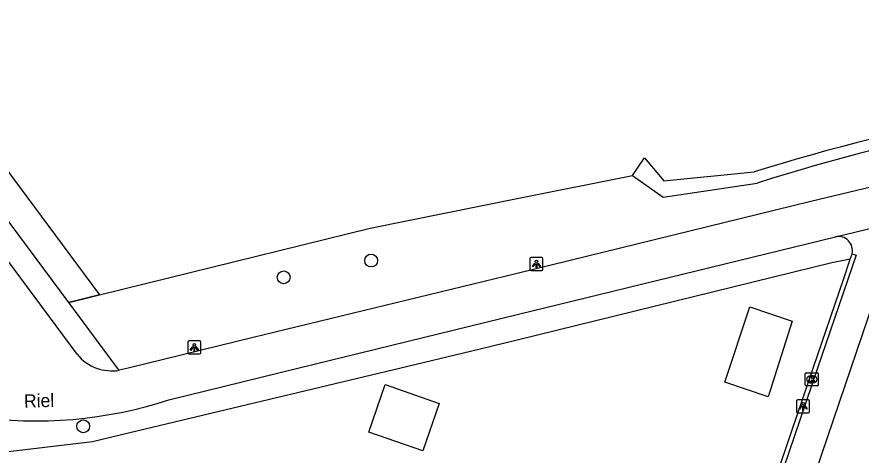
# Model space of a CAD drawing. Extents: x 163427 to 164190, y 380331 to 381641.
# Drawn here: x 163961.9 to 164026.2, y 380993.4 to 381026.8 of the extents above; entities that cross this region are included whole.
import ezdxf

# ---------------------------------------------------------------- set-up
doc = ezdxf.new("R2010")
doc.units = 0
for name, color, linetype in [('IMGEO_Boom', 7, 'Continuous'), ('IMGEO_Fietspad_open', 7, 'Continuous'), ('IMGEO_Groenvoorziening', 7, 'Continuous'), ('IMGEO_Hek', 7, 'Continuous'), ('IMGEO_Kolk', 7, 'Continuous'), ('IMGEO_Lichtpunt', 7, 'Continuous'), ('IMGEO_Openbare_ruimte_label', 7, 'Continuous'), ('IMGEO_Pand', 7, 'Continuous'), ('IMGEO_Rijbaan_lokaal_open', 7, 'Continuous'), ('IMGEO_Voetpad_open', 7, 'Continuous'), ('IMGEO_Waterloop', 7, 'Continuous')]:
    doc.layers.add(name, color=color, linetype=linetype)

msp = doc.modelspace()

# ---------------------------------------------------------------- linework, layer by layer
at = {"layer": 'IMGEO_Boom'}
for centre in [(163988.865, 381008.202), (163982.196, 381006.926), (163966.911, 380995.571)]:
    msp.add_circle(centre, 0.489, dxfattribs=at)
at = {"layer": 'IMGEO_Fietspad_open'}
for points in [[(163966.446, 381001.057), (163930.523, 381049.491), (163926.717, 381054.622), (163925.556, 381056.187)], [(164038.024, 381016.446), (164022.398, 381012.694), (164000, 381007.225), (163979.878, 381002.33), (163970.33, 381000), (163969.654, 380999.835)], [(164024.271, 381010.02), (164029.636, 381011.297)], [(163973.446, 380997.596), (163983.281, 381000), (164000, 381004.087), (164024.271, 381010.02)]]:
    msp.add_lwpolyline(points, dxfattribs=at)
for centre, radius, start, end in [((163969.159, 381003.295), 3.517, 219.52759, 249.55059), ((163969.115, 381003.289), 3.495, 250.18958, 278.87643), ((163963.36, 381028.213), 32.235, 261.55505, 288.23327)]:
    msp.add_arc(centre, radius, start, end, dxfattribs=at)
at = {"layer": 'IMGEO_Groenvoorziening'}
for points in [[(163936.474, 381048.305), (163965.302, 381009.415), (163968.142, 381005.578)], [(163968.142, 381005.578), (163988.801, 381010.675), (164000, 381012.925), (164008.796, 381014.693)], [(164025.394, 381008.299), (164023.996, 381008.024), (164000, 381002.141), (163996.432, 381001.266), (163991.135, 381000), (163970.466, 380995.06), (163967.625, 380994.381), (163961.405, 380993.65), (163960.215, 380993.613), (163954.592, 380993.795), (163949.019, 380994.564), (163937.098, 380997.759), (163924.687, 381000), (163899.949, 381004.467), (163899.243, 381001.078)], [(163968.142, 381005.578), (163965.814, 381005.004)]]:
    msp.add_lwpolyline(points, dxfattribs=at)
at = {"layer": 'IMGEO_Hek'}
msp.add_lwpolyline([(163965.814, 381005.004), (163968.142, 381005.578)], dxfattribs=at)
at = {"layer": 'IMGEO_Kolk'}
for p, q in [((164021.963, 380998.727), (164021.963, 380999.579)), ((164022.038, 380999.653), (164022.89, 380999.653)), ((164022.964, 380999.579), (164022.964, 380998.727)), ((164022.451, 380999.433), (164022.476, 380999.433)), ((164022.89, 380998.653), (164022.038, 380998.653)), ((164022.474, 380998.873), (164022.449, 380998.873))]:
    msp.add_line(p, q, dxfattribs=at)
for points in [[(164021.963, 380998.727), (164021.963, 380999.579)], [(164022.038, 380999.653), (164022.89, 380999.653)], [(164022.964, 380999.579), (164022.964, 380998.727)], [(164022.284, 380999.353), (164022.407, 380999.353), (164022.407, 380999.202), (164022.537, 380999.353), (164022.701, 380999.353), (164022.555, 380999.202), (164022.708, 380998.953), (164022.556, 380998.953), (164022.471, 380999.117), (164022.407, 380999.05), (164022.407, 380998.953), (164022.284, 380998.953), (164022.284, 380999.353)], [(164022.89, 380998.653), (164022.038, 380998.653)]]:
    msp.add_lwpolyline(points, dxfattribs=at)
for centre, start, end in [((164022.04, 380999.577), 91.55205, 178.44795), ((164022.04, 380999.577), 91.55205, 178.44795), ((164022.888, 380999.577), 1.55205, 88.44795), ((164022.888, 380999.577), 1.55205, 88.44795), ((164022.04, 380998.729), 181.55205, 268.44795), ((164022.04, 380998.729), 181.55205, 268.44795), ((164022.888, 380998.729), 271.55205, 358.44795), ((164022.888, 380998.729), 271.55205, 358.44795)]:
    msp.add_arc(centre, 0.0765, start, end, dxfattribs=at)
for centre, major_axis, ratio, start_param, end_param in [((164022.45, 380999.153), (-0.387, 0.002), 0.722429, 4.712389, 7.853982), ((164022.475, 380999.153), (-0.39, 0.002), 0.717154, 1.570796, 4.712389)]:
    msp.add_ellipse(centre, major_axis=major_axis, ratio=ratio, start_param=start_param, end_param=end_param, dxfattribs=at)
at = {"layer": 'IMGEO_Lichtpunt'}
for p, q in [((164000.97, 381008.347), (164000.97, 381007.54)), ((164000.97, 381008.347), (164000.97, 381007.54)), ((164001.872, 381008.442), (164001.064, 381008.442)), ((164001.872, 381008.442), (164001.064, 381008.442)), ((164001.966, 381007.54), (164001.966, 381008.347)), ((164001.966, 381007.54), (164001.966, 381008.347)), ((164001.064, 381007.446), (164001.872, 381007.446)), ((164001.064, 381007.446), (164001.872, 381007.446)), ((163974.883, 381001.984), (163974.883, 381001.177)), ((163974.883, 381001.984), (163974.883, 381001.177)), ((163975.785, 381002.079), (163974.977, 381002.079)), ((163975.785, 381002.079), (163974.977, 381002.079)), ((163975.879, 381001.177), (163975.879, 381001.984)), ((163975.879, 381001.177), (163975.879, 381001.984)), ((163974.977, 381001.083), (163975.785, 381001.083)), ((163974.977, 381001.083), (163975.785, 381001.083)), ((164021.304, 380997.491), (164021.304, 380996.684)), ((164021.304, 380997.491), (164021.304, 380996.684)), ((164022.206, 380997.586), (164021.398, 380997.586)), ((164022.206, 380997.586), (164021.398, 380997.586)), ((164022.3, 380996.684), (164022.3, 380997.491)), ((164022.3, 380996.684), (164022.3, 380997.491)), ((164021.398, 380996.59), (164022.206, 380996.59)), ((164021.398, 380996.59), (164022.206, 380996.59))]:
    msp.add_line(p, q, dxfattribs=at)
for points in [[(164001.344, 381008.011), (164001.383, 381007.983), (164001.195, 381007.721), (164001.157, 381007.748), (164001.344, 381008.011)], [(164001.446, 381007.963), (164001.493, 381007.963), (164001.493, 381007.641), (164001.446, 381007.641), (164001.446, 381007.963)], [(164001.556, 381007.983), (164001.594, 381008.01), (164001.781, 381007.748), (164001.742, 381007.72), (164001.556, 381007.983)], [(163975.257, 381001.648), (163975.296, 381001.62), (163975.108, 381001.358), (163975.07, 381001.385), (163975.257, 381001.648)], [(163975.359, 381001.6), (163975.406, 381001.6), (163975.406, 381001.278), (163975.359, 381001.278), (163975.359, 381001.6)], [(163975.469, 381001.62), (163975.507, 381001.647), (163975.694, 381001.385), (163975.655, 381001.357), (163975.469, 381001.62)], [(164021.678, 380997.155), (164021.717, 380997.127), (164021.529, 380996.865), (164021.491, 380996.892), (164021.678, 380997.155)], [(164021.78, 380997.107), (164021.827, 380997.107), (164021.827, 380996.785), (164021.78, 380996.785), (164021.78, 380997.107)], [(164021.89, 380997.127), (164021.928, 380997.154), (164022.115, 380996.892), (164022.076, 380996.864), (164021.89, 380997.127)]]:
    msp.add_lwpolyline(points, dxfattribs=at)
for centre in [(164001.469, 381008.145), (163975.382, 381001.782), (164021.803, 380997.289)]:
    msp.add_circle(centre, 0.0994, dxfattribs=at)
for centre, start, end in [((164001.064, 381008.347), 90, 180), ((164001.064, 381008.347), 90, 180), ((164001.872, 381008.347), 0, 90), ((164001.872, 381008.347), 0, 90), ((164001.064, 381007.54), 180, 270), ((164001.064, 381007.54), 180, 270), ((164001.872, 381007.54), 270, 0), ((164001.872, 381007.54), 270, 360), ((163974.977, 381001.984), 90, 180), ((163974.977, 381001.984), 90, 180), ((163975.785, 381001.984), 0, 90), ((163975.785, 381001.984), 0, 90), ((163974.977, 381001.177), 180, 270), ((163974.977, 381001.177), 180, 270), ((163975.785, 381001.177), 270, 0), ((163975.785, 381001.177), 270, 360), ((164021.398, 380997.491), 90, 180), ((164021.398, 380997.491), 90, 180), ((164022.206, 380997.491), 0, 90), ((164022.206, 380997.491), 0, 90), ((164021.398, 380996.684), 180, 270), ((164021.398, 380996.684), 180, 270), ((164022.206, 380996.684), 270, 0), ((164022.206, 380996.684), 270, 360)]:
    msp.add_arc(centre, 0.0946, start, end, dxfattribs=at)
at = {"layer": 'IMGEO_Pand'}
for points in [[(164015.845, 380998.943), (164017.734, 381004.668), (164020.98, 381003.59), (164019.137, 380997.818), (164015.845, 380998.943)], [(163988.683, 380995.119), (163989.936, 380998.744), (163994.064, 380997.317), (163992.811, 380993.692), (163988.683, 380995.119)]]:
    msp.add_lwpolyline(points, dxfattribs=at)
at = {"layer": 'IMGEO_Rijbaan_lokaal_open'}
for points in [[(164025.538, 381008.722), (164025.84, 381008.617), (164022.906, 381000), (164015.09, 380977.048)], [(164025.394, 381008.299), (164025.538, 381008.722)], [(164014.792, 380977.145), (164022.57, 381000), (164024.898, 381006.842), (164025.394, 381008.299)]]:
    msp.add_lwpolyline(points, dxfattribs=at)
at = {"layer": 'IMGEO_Voetpad_open'}
for points in [[(163965.814, 381005.004), (163933.77, 381048.138)], [(164028.463, 381008.901), (164025.441, 381000), (164017.396, 380976.301)], [(163969.654, 380999.835), (163969.531, 381000), (163965.814, 381005.004)]]:
    msp.add_lwpolyline(points, dxfattribs=at)
msp.add_arc((164024.49, 381008.966), 1.076, 346.88338, 101.73176, dxfattribs=at)
at = {"layer": 'IMGEO_Waterloop'}
for points in [[(164008.796, 381014.693), (164009.7, 381016.026), (164011.181, 381014.28), (164018.059, 381014.961)], [(164008.796, 381014.693), (164011.14, 381013.031), (164018.294, 381014.111)]]:
    msp.add_lwpolyline(points, dxfattribs=at)
for centre, radius, start, end in [((164066.317, 380859.787), 162.505, 94.22056, 107.2752), ((164063.698, 380870.896), 150.24, 93.46108, 107.59041)]:
    msp.add_arc(centre, radius, start, end, dxfattribs=at)

# ---------------------------------------------------------------- texts
at = {"layer": 'IMGEO_Openbare_ruimte_label'}
msp.add_text('Riel', height=1, rotation=1.37483, dxfattribs=at).set_placement((163962.406, 380996.995))

doc.saveas('drawing.dxf')
